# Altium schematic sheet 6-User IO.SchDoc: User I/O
size B; CompanyName: NGRF; Address1: 2130 Howard Drive W; Address2: North Mankato, MN 56003; Address3: www.nextgenrf.com; Revision: 2; SheetNumber: 6; SheetTotal: 7; ProjName: BytePipe X9002_HDK
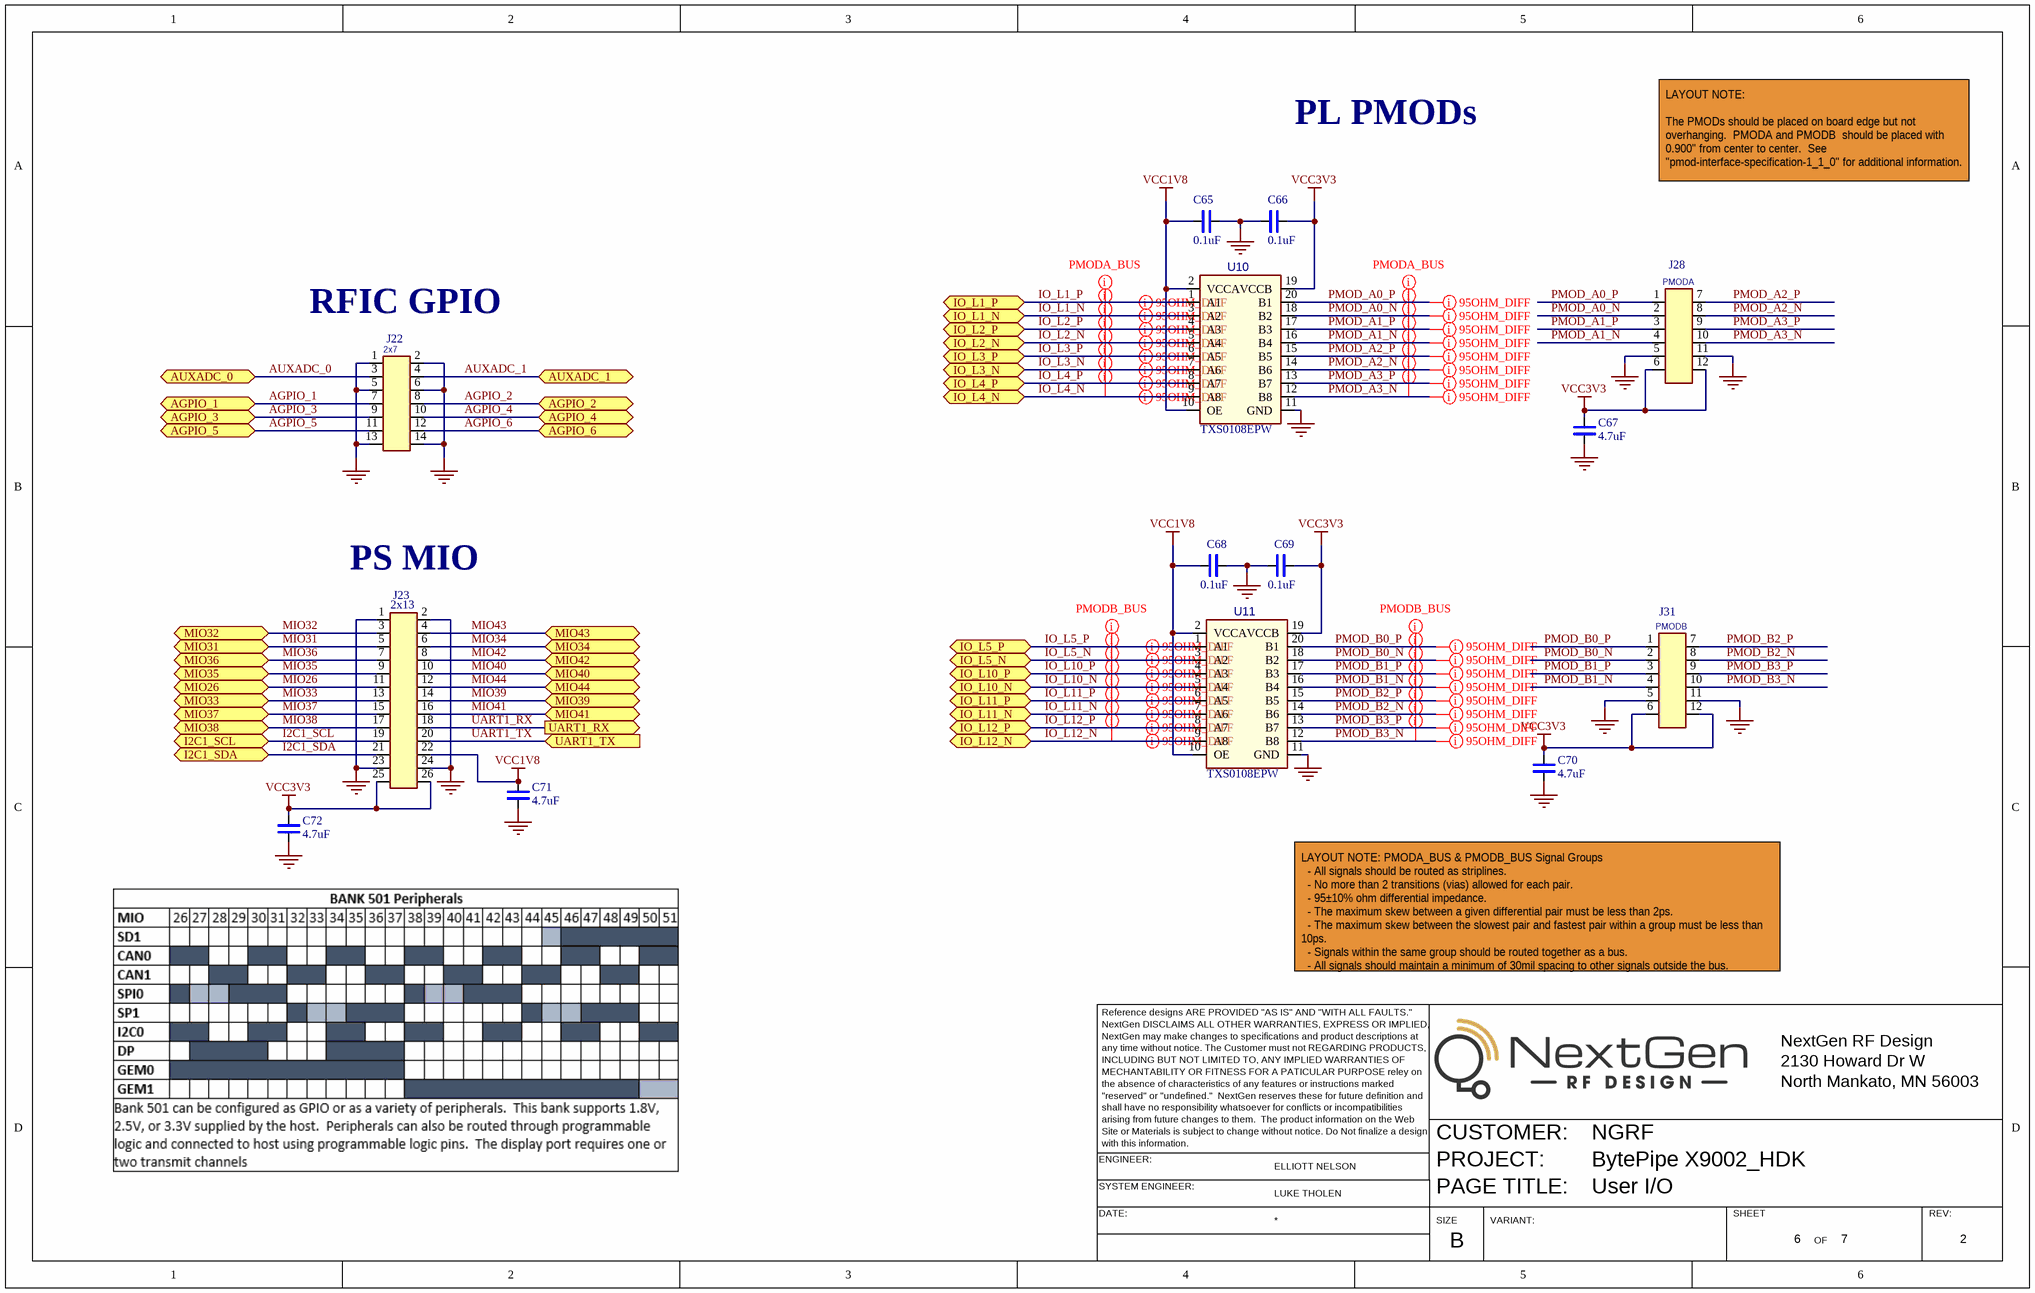
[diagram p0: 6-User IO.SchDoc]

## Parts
C65  value 0.1uF  [SM/0402/CAP]  (hidden comment: CAP_CERAMIC_0402)
C66  value 0.1uF  [SM/0402/CAP]  (hidden comment: CAP_CERAMIC_0402)
C67  value 4.7uF  [SM/0402/CAP]  (hidden comment: CAP_CERAMIC_0402)
C68  value 0.1uF  [SM/0402/CAP]  (hidden comment: CAP_CERAMIC_0402)
C69  value 0.1uF  [SM/0402/CAP]  (hidden comment: CAP_CERAMIC_0402)
C70  value 4.7uF  [SM/0402/CAP]  (hidden comment: CAP_CERAMIC_0402)
C71  value 4.7uF  [SM/0402/CAP]  (hidden comment: CAP_CERAMIC_0402)
C72  value 4.7uF  [SM/0402/CAP]  (hidden comment: CAP_CERAMIC_0402)
J22  value 2x7  [CON/100SP/2X7P/VT/038_A]  (hidden comment: CON_100SP_2X7P_VT)
J23  value 2x13  [CON/100SP/2X13P/038_A]  (hidden comment: CON_100SP_2X13P_VERT)
J28  value PMODA  [CON/SAMTEC/SSW/2X6/RA_A/PMOD]  (hidden comment: CON_100SP_2X6P_RA_PMOD)
J31  value PMODB  [CON/SAMTEC/SSW/2X6/RA_A/PMOD]  (hidden comment: CON_100SP_2X6P_RA_PMOD)
U10  value TXS0108EPW  [SM/TSSOP20_6.5X6.4MM]  (hidden comment: IC_TXS0108_TSSOP-20)
U11  value TXS0108EPW  [SM/TSSOP20_6.5X6.4MM]  (hidden comment: IC_TXS0108_TSSOP-20)

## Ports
AGPIO_1 (bidir), AGPIO_2 (bidir), AGPIO_3 (bidir), AGPIO_4 (bidir), AGPIO_5 (bidir), AGPIO_6 (bidir), AUXADC_0 (bidir), AUXADC_1 (bidir), I2C1_SCL (bidir), I2C1_SDA (bidir), IO_L1_N (bidir), IO_L1_P (bidir), IO_L2_N (bidir), IO_L2_P (bidir), IO_L3_N (bidir), IO_L3_P (bidir), IO_L4_N (bidir), IO_L4_P (bidir), IO_L5_N (bidir), IO_L5_P (bidir), IO_L10_N (bidir), IO_L10_P (bidir), IO_L11_N (bidir), IO_L11_P (bidir), IO_L12_N (bidir), IO_L12_P (bidir), MIO26 (bidir), MIO31 (bidir), MIO32 (bidir), MIO33 (bidir), MIO34 (bidir), MIO35 (bidir), MIO36 (bidir), MIO37 (bidir), MIO38 (bidir), MIO39 (bidir), MIO40 (bidir), MIO41 (bidir), MIO42 (bidir), MIO43 (bidir), MIO44 (bidir), UART1_RX (out), UART1_TX (in)

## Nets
GND: C65.2(N2) C66.1(N1) C67.2(N2) C68.2(N2) C69.1(N1) C70.2(N2) C71.2(N2) C72.2(N2) J22.1(N1) J22.2(N2) J22.5(N5) J22.6(N6) J22.13(N13) J22.14(N14) J23.1(N1) J23.2(N2) J23.23(N23) J23.24(N24) J28.5(N5) J28.11(N11) J31.5(N5) J31.11(N11) U10.11(GND) U11.11(GND)
VCC1V8: C65.1(N1) C68.1(N1) C71.1(N1) J23.22(N22) U10.2(VCCA) U10.10(OE) U11.2(VCCA) U11.10(OE)
VCC3V3: C66.2(N2) C67.1(N1) C69.2(N2) C70.1(N1) C72.1(N1) J23.25(N25) J23.26(N26) J28.6(N6) J28.12(N12) J31.6(N6) J31.12(N12) U10.19(VCCB) U11.19(VCCB)
AGPIO_1: J22.7(N7) ; port AGPIO_1
AGPIO_2: J22.8(N8) ; port AGPIO_2
AGPIO_3: J22.9(N9) ; port AGPIO_3
AGPIO_4: J22.10(N10) ; port AGPIO_4
AGPIO_5: J22.11(N11) ; port AGPIO_5
AGPIO_6: J22.12(N12) ; port AGPIO_6
AUXADC_0: J22.3(N3) ; port AUXADC_0
AUXADC_1: J22.4(N4) ; port AUXADC_1
I2C1_SCL: J23.19(N19) ; port I2C1_SCL
I2C1_SDA: J23.21(N21) ; port I2C1_SDA
IO_L1_N: U10.3(A2) ; port IO_L1_N
IO_L1_P: U10.1(A1) ; port IO_L1_P
IO_L2_N: U10.5(A4) ; port IO_L2_N
IO_L2_P: U10.4(A3) ; port IO_L2_P
IO_L3_N: U10.7(A6) ; port IO_L3_N
IO_L3_P: U10.6(A5) ; port IO_L3_P
IO_L4_N: U10.9(A8) ; port IO_L4_N
IO_L4_P: U10.8(A7) ; port IO_L4_P
IO_L5_N: U11.3(A2) ; port IO_L5_N
IO_L5_P: U11.1(A1) ; port IO_L5_P
IO_L10_N: U11.5(A4) ; port IO_L10_N
IO_L10_P: U11.4(A3) ; port IO_L10_P
IO_L11_N: U11.7(A6) ; port IO_L11_N
IO_L11_P: U11.6(A5) ; port IO_L11_P
IO_L12_N: U11.9(A8) ; port IO_L12_N
IO_L12_P: U11.8(A7) ; port IO_L12_P
MIO26: J23.11(N11) ; port MIO26
MIO31: J23.5(N5) ; port MIO31
MIO32: J23.3(N3) ; port MIO32
MIO33: J23.13(N13) ; port MIO33
MIO34: J23.6(N6) ; port MIO34
MIO35: J23.9(N9) ; port MIO35
MIO36: J23.7(N7) ; port MIO36
MIO37: J23.15(N15) ; port MIO37
MIO38: J23.17(N17) ; port MIO38
MIO39: J23.14(N14) ; port MIO39
MIO40: J23.10(N10) ; port MIO40
MIO41: J23.16(N16) ; port MIO41
MIO42: J23.8(N8) ; port MIO42
MIO43: J23.4(N4) ; port MIO43
MIO44: J23.12(N12) ; port MIO44
PMOD_A0_N: J28.2(N2) U10.18(B2)
PMOD_A0_P: J28.1(N1) U10.20(B1)
PMOD_A1_N: J28.4(N4) U10.16(B4)
PMOD_A1_P: J28.3(N3) U10.17(B3)
PMOD_A2_N: J28.8(N8) U10.14(B6)
PMOD_A2_P: J28.7(N7) U10.15(B5)
PMOD_A3_N: J28.10(N10) U10.12(B8)
PMOD_A3_P: J28.9(N9) U10.13(B7)
PMOD_B0_N: J31.2(N2) U11.18(B2)
PMOD_B0_P: J31.1(N1) U11.20(B1)
PMOD_B1_N: J31.4(N4) U11.16(B4)
PMOD_B1_P: J31.3(N3) U11.17(B3)
PMOD_B2_N: J31.8(N8) U11.14(B6)
PMOD_B2_P: J31.7(N7) U11.15(B5)
PMOD_B3_N: J31.10(N10) U11.12(B8)
PMOD_B3_P: J31.9(N9) U11.13(B7)
UART1_RX: J23.18(N18) ; port UART1_RX
UART1_TX: J23.20(N20) ; port UART1_TX

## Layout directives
net class PMODA_BUS: IO_L1_N, IO_L1_P, IO_L2_N, IO_L2_P, IO_L3_N, IO_L3_P, IO_L4_N, IO_L4_P, PMOD_A0_N, PMOD_A0_P, PMOD_A1_N, PMOD_A1_P, PMOD_A2_N, PMOD_A2_P, PMOD_A3_N, PMOD_A3_P
differential pair; Impedance: 90 Ohms; differential pair class 95OHM_DIFF: IO_L1_N, IO_L1_P, IO_L2_N, IO_L2_P, IO_L3_N, IO_L3_P, IO_L4_N, IO_L4_P, IO_L5_N, IO_L5_P, IO_L10_N, IO_L10_P, IO_L11_N, IO_L11_P, IO_L12_N, IO_L12_P, PMOD_A0_N, PMOD_A0_P, PMOD_A1_N, PMOD_A1_P, PMOD_A2_N, PMOD_A2_P, PMOD_A3_N, PMOD_A3_P, PMOD_B0_N, PMOD_B0_P, PMOD_B1_N, PMOD_B1_P, PMOD_B2_N, PMOD_B2_P, PMOD_B3_N, PMOD_B3_P
net class PMODB_BUS: IO_L5_N, IO_L5_P, IO_L10_N, IO_L10_P, IO_L11_N, IO_L11_P, IO_L12_N, IO_L12_P, PMOD_B0_N, PMOD_B0_P, PMOD_B1_N, PMOD_B1_P, PMOD_B2_N, PMOD_B2_P, PMOD_B3_N, PMOD_B3_P

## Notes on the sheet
- PL PMODs
- LAYOUT NOTE:
  The PMODs should be placed on board edge but not overhanging.  PMODA and PMODB  should be placed with 0.900" from center to center.  See "pmod-interface-specification-1_1_0" for additional information.
- (near J22) RFIC GPIO
- (near J23) PS MIO
- LAYOUT NOTE: PMODA_BUS & PMODB_BUS Signal Groups
  - All signals should be routed as striplines.
  - No more than 2 transitions (vias) allowed for each pair.
  - 95±10% ohm differential impedance.
  - The maximum skew between a given differential pair must be less than 2ps.
  - The maximum skew between the slowest pair and fastest pair within a group must be less than 10ps.
  - Signals within the same group should be routed together as a bus.
  - All signals should maintain a minimum of 30mil spacing to other signals outside the bus.
- Reference designs ARE PROVIDED "AS IS" AND "WITH ALL FAULTS."
- NextGen DISCLAIMS ALL OTHER WARRANTIES, EXPRESS OR IMPLIED,
- NextGen may make changes to specifications and product descriptions at
- NextGen RF Design
- any time without notice. The Customer must not REGARDING PRODUCTS,
- INCLUDING BUT NOT LIMITED TO, ANY IMPLIED WARRANTIES OF
- MECHANTABILITY OR FITNESS FOR A PATICULAR PURPOSE reley on
- "reserved" or "undefined."  NextGen reserves these for future definition and
- the absence of characteristics of any features or instructions marked
- shall have no responsibility whatsoever for conflicts or incompatibilities
- 2130 Howard Dr W
- North Mankato, MN 56003
- ENGINEER:
- Site or Materials is subject to change without notice. Do Not finalize a design
- with this information.
- arising from future changes to them.  The product information on the Web
- ELLIOTT NELSON
- CUSTOMER:
- PROJECT:
- SYSTEM ENGINEER:
- DATE:
- LUKE THOLEN
- SIZE
- PAGE TITLE:
- VARIANT:
- SHEET
- OF
- REV:
- B

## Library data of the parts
C65 C66 C68 C69 = CAP_CERAMIC_0402: CAP CER 0.1UF 25V X7R 0402; TOL: ±10%; OEM#: CL05B104KA5NNNC; OEM NAME: Samsung
C67 C70-C72 = CAP_CERAMIC_0402: CAP CER 4.7UF 10V X5R 0402; TOL: ±20%; OEM#: CL05A475MP5NRNC; OEM NAME: Samsung
J22 = CON_100SP_2X7P_VT: Connector Header Through Hole 14 position 0.100" (2.54mm); OEM#: 2011-2X07TSB; OEM NAME: Harwin Inc.
J23 = CON_100SP_2X13P_VERT: PIN HEADER, DOUBLE ROW 26 PIN, S; OEM#: M20-9981345; OEM NAME: Harwin Inc.
J28 J31 = CON_100SP_2X6P_RA_PMOD: Header, 100 mil, 2x6, Right Angle, PMOD pin out.; OEM#: SSW-106-02-T-D-RA; OEM NAME: SAMTEC
U10 U11 = IC_TXS0108_TSSOP-20: IC TRNSLTR BIDIRECTIONAL 20VQFN; OEM NAME: Texas Instruments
